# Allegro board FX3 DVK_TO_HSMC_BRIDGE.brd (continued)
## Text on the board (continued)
Ref Des/Silkscreen Top: I2S_CLK | I2C_SDA | I2S_SD | _PPORT | _CTL15 | PMODE1 | INT_N | _CON | I2C_SCL_PPORT | RESET_N_CON | PMODE0_CON | PMODE2_CON | VIO1_HDR | I2S_MCLK | I2S_WP | CTL9 | CTL11 | CTL7 | CTL5 | CTL3 | CTL1 | GND | FX3 DVK TO HSMC BRIDGE | CTL12 | CTL10 | CTL8 | CTL6 | CTL4 | CTL2 | CTL0 | DQ22 | DQ20 | DQ19 | DQ18 | DQ16 | DQ17 | PCLK | DQ31 | DQ30 | DQ29 | DQ28 | DQ27 | DQ26 | DQ25 | DQ24 | DQ23 | DQ21 | DQ15 | DQ13 | DQ12 | DQ11 | DQ10 | DQ09 | DQ08 | DQ07 | DQ06 | DQ05 | DQ04 | DQ03 | DQ02 | DQ01 | DQ00 | DQ14 | V5P0_HDR | AGILE SOLUTIONS
PAGE_OUTLINE: D | C | B | A | 8 | 7 | 6 | 5 | 4 | 3 | 2 | 1 | CAD | DATA | DO NOT MANUALLY | UPDATE
User.21: NOTES: UNLESS OTHERWISE SPECIFIED. | 1. FABRICATE IN ACCORDANCE WITH LATEST IPC-6012 SPECIFICATIONS, CLASS 2. | 2. ACCEPTABILITY SHALL BE BASED ON LATEST IPC-A-600 SPECIFICATIONS, CLASS 2. | 3. ALL BASE MATERIAL SHALL BE IN ACCORDANCE WITH LATEST IPC-4101/126 SPECIFICATIONS. | 4. FLAMMABILITY RATINGS SHALL BE IN ACCORDANCE WITH UL 94V-0 (0R 94V-1 IF 94V-0 | 5. FINISH: ELECTROLESS NICKEL IMMERSION GOLD (ENIG) WITH A NORMAL 3-7 MICRO-INCH IMMERSION GOLD | 6. FRONT AND BACK PATTERN SHALL REGISTER WITHIN .003". | 7. HOLE CENTERS LOCATED ON PADS AND CENTERED WITHIN .003" RTP. | 8. CONDUCTOR EDGES TO BE FREE OF LOOSE SILVERS AND ROUGH EDGES. | 9. END PRODUCT CONDUCTOR WIDTHS AND CIRCUIT FEATURES SHALL NOT VARY MORE | 10.THE CONSTRUCTION AND INTRA-LAYER SPACING SHALL BE AS DEFINED IN DETAIL "A". | 11.ALL TOOLING HOLES MUST BE DRILLED DURING PRIMARY DRILL STAGE, SECONDARY DRILL | 12.BOW AND TWIST SHALL NOT EXCEED 0.0075" PER INCH OF LENGTH. | 13.ALL PLATED THRU HOLES AND CONDUCTIVE SURFACES SHALL BE PLATED WITH A MINIMUM | 14.HOLE SIZES ARE AFTER PLATING. | 15.PRIOR TO SOLDERMASK, THE BOARD SHALL BE CLEANED AND FREE OF CONTAMINANTS OR RESIDUES. | 16.SOLDERMASK: SHALL BE GREEN LIQUID PHOTO-IMGEABLE (LPI) PER LATEST IPC-SM-840 | 17.THE LEGEND SHALL BE PRINTED USING NON-CONDUCTIVE PERMANENT EPOXY INK, | 18.PRINTING REGISTRATION ALLOWANCE IS 0.005". THERE SHALL BE NO INK ON | 19.ALL BOARDS SHALL BE ELECTRICALLY TESTED TO THE NET LIST USING IPC-D-356 FOR | 20.THE PHOTO-TOOL MAY BE COMPENSATED FOR ETCHING ALLOWANCES ONLY. A 1-1 RELATIONSHIP | 21.ALL PROCESSES ARE TO MAINTAIN COMPLIANCE WITH ROHS DIRECTIVE 2002/95/EC. | 22.THE FABRICATED BOARD SHOULD BE RoHS COMPLIANT. | 23.BOARD CONSISTS CUT-OUTS. THOSE DIMENSION ARE PRESENT IN THE  DETAIL B | 24. MINIMUM CONDUCTOR WIDTH: 4.5 MILS | 25. SILK SCREEN SHOULD BE RETAIN,  IF ITS OVERLAP ON VIA | 26. THE ENTER BOARD SHOULD BE 50E IMPEDENCE MATCHED | MINIMUM SPACING:4.5 MILS | MINIMUM DRILL-PAD SIZES :10-20 MILS. | AFTER FABRICATION THE TOTAL LAYER COUNT SHALL BE 6 | CORE MATERIALS ARE REGISTERED LAMINATES PER LATEST IPC-4121 SPECIFICATIONS. | MATERIAL TO BE 61.268 +/-10% THICK EPOXY GLASS, ISOLA 370 HR OR | EQUIVALENT WITH A MINIMUM TG OF 170C. | MATERIAL IS UNAVAILABLE). AS MANDATED BY STANDARDS UL61010A-1, IEC61010-1, | AND EN61010-1. | OVER 150-200 MICRO-INCH IMMERSION NICKEL ON ALL EXPOSED TRACES AND FEATURES. | THAN 0.002" FROM THE 1:1 DIMENSIONS OF THE MASTER PATTERN. | STAGE SHALL NOT BE PERMITTED. | THICKNESS OF .001" COPPER. | SPECIFICATIONS, TYPE-B, CLASS2 . REGISTRATION ALLOWANCE IS 0.003" RTP. | COLOR: WHITE. | ANY SOLDER PAD OR LAND. | CONTINUITY OPENS AND SHORTS. | MUST BE APPARENT BETWEEN GERBERS SUBMITTED AND FINAL PRODUCT. IT IS PROHIBITED TO | IMPLEMENT THE USE OF FILLETING OR TEAR DROP TECHNOLOGY ON VIAS IN PREVENTING HOLE | BREAK OUT. EDITS TO THE GERBER DATA FOR COPPER THIEVING SHALL NOT BE PERMITTED. NO | CHANGES CAN BE MADE WITHOUT A DEVIATION NOTICE. | FX3 DVK TO HSMC BRIDGE | XXXXXXXXXX | SENSITIVE ELECTRONIC DEVICES-CLASS 1 | CAUTION
User.36: L01 TOP SIDE
User.37: L02 GND PLANE 1
User.38: L3 SIG 1
User.39: L4 SIG 2
User.40: L05 PWR PLANE 1
User.41: L06 BOTTOM
User.42: L7 SIG 3
User.43: L8 SIG 4
User.44: L9 PWR PLANE 2
User.45: PREPERG  0.0040 | PREPERG  0.0320 | CORE  0.0060 | CORE 0.0060 | COPPER WEIGHT = 1.OZ | COPPER WEIGHT = 1 OZ | TOP SILKSCREEN | TOP SOLDERMASK | LAYER 1-TOP | LAYER 2-GND PLANE 1 | COPPER WEIGHT = 1 0Z | LAYER 3-SIG1 | LAYER 4-SIG2 | LAYER 5-PWR PLANE 1 | LAYER 6-BOTTOM | BOTTOM SOLDERMASK | BOTTOM SILKSCREEN | 0.061268  INCH+/- 10% | LAYER STACK UP | SCALE : NONE | FIGURE | SIZE | 10.0 | 40.0 | DRILL CHART: TOP to BOTTOM | ALL UNITS ARE IN MILS | TOLERANCE | +3.0/-3.0 | PLATED | NON-PLATED | QTY | 308 | 4 | FX3DVK TO HSMC BRIDGE | DOCUMENT NAME: | P/N-XXXXXXXXXX | TOP SILK | ASSMB NO--XXXXXXXXXX | REV:1.0 | TOP MASK | TOP PASTE | BOTTOM MASK | BOTTOM SILK | BOTTOM PASTE | TOP ASSEMBLY | DRILL DRAWING | BOTTOM ASSEMBLY | L04 BOTTOM SIDE
